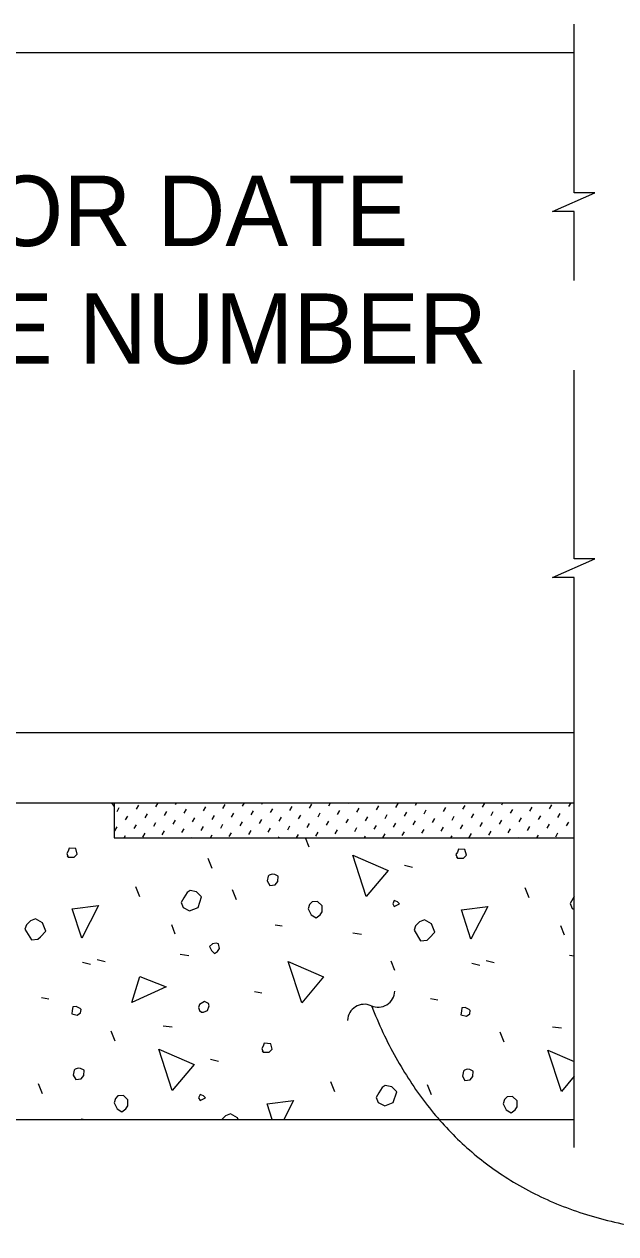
# Model space of a CAD drawing. Extents: x 130583.6 to 130653, y 88618.2 to 88652.9.
# Drawn here: x 130605.355 to 130607.456, y 88633.745 to 88638.043 of the extents above; entities that cross this region are included whole.
import ezdxf

# ---------------------------------------------------------------- set-up
doc = ezdxf.new("R2010")
doc.units = 0
for name, color, linetype in [('Dimension', 7, 'Continuous'), ('Miscellaneous', 7, 'Continuous'), ('TextStructures', 7, 'Continuous'), ('TrafBarrierConc', 7, 'Continuous')]:
    doc.layers.add(name, color=color, linetype=linetype)

msp = doc.modelspace()

# ---------------------------------------------------------------- linework, layer by layer
at = {"layer": 'Dimension'}
for points in [[(130607.3086, 88637.1321), (130607.3086, 88637.3778), (130607.2311, 88637.3778), (130607.3811, 88637.444), (130607.3086, 88637.444), (130607.3086, 88638.0434)], [(130607.3086, 88636.4382), (130607.3086, 88636.8145)], [(130607.3086, 88634.0518), (130607.3086, 88636.0774), (130607.2311, 88636.0774), (130607.3811, 88636.1437), (130607.3086, 88636.1437), (130607.3086, 88636.4382)]]:
    msp.add_lwpolyline(points, dxfattribs=at)
for centre, start, end in [((130606.6114, 88634.61), 245.9128, 357.64), ((130606.5627, 88634.5011), 65.9128, 177.64)]:
    msp.add_arc(centre, 0.0596, start, end, dxfattribs=at)
msp.add_open_spline([(130606.5877, 88634.5559), (130606.9109, 88633.7452), (130607.8406, 88633.7452)], degree=2, dxfattribs=at)
at = {"layer": 'Miscellaneous'}
for p, q in [((130605.8227, 88635.2623), (130605.8308, 88635.2763)), ((130605.8918, 88635.2704), (130605.8955, 88635.2768)), ((130606.1298, 88635.2642), (130606.1371, 88635.2768)), ((130606.199, 88635.2723), (130606.2016, 88635.2768)), ((130606.3679, 88635.258), (130606.376, 88635.272)), ((130606.437, 88635.2661), (130606.4432, 88635.2768)), ((130606.5062, 88635.2742), (130606.5077, 88635.2768)), ((130606.6751, 88635.2598), (130606.6832, 88635.2738)), ((130606.7442, 88635.2679), (130606.7493, 88635.2768)), ((130606.8134, 88635.276), (130606.8138, 88635.2768)), ((130606.9822, 88635.2617), (130606.9903, 88635.2757)), ((130607.0514, 88635.2698), (130607.0554, 88635.2768)), ((130607.2894, 88635.2636), (130607.297, 88635.2768)), ((130605.6843, 88635.2461), (130605.6924, 88635.2601)), ((130605.7149, 88635.2156), (130605.723, 88635.2296)), ((130605.7535, 88635.2542), (130605.7616, 88635.2682)), ((130605.784, 88635.2237), (130605.7921, 88635.2377)), ((130605.8532, 88635.2318), (130605.8613, 88635.2458)), ((130605.9224, 88635.2399), (130605.9305, 88635.2539)), ((130605.9915, 88635.248), (130605.9996, 88635.262)), ((130606.022, 88635.2175), (130606.0302, 88635.2314)), ((130606.0607, 88635.2561), (130606.0688, 88635.2701)), ((130606.0912, 88635.2256), (130606.0993, 88635.2396)), ((130606.1604, 88635.2337), (130606.1685, 88635.2477)), ((130606.2295, 88635.2418), (130606.2376, 88635.2558)), ((130606.2987, 88635.2499), (130606.3068, 88635.2639)), ((130606.3292, 88635.2193), (130606.3373, 88635.2333)), ((130606.3984, 88635.2274), (130606.4065, 88635.2414)), ((130606.4676, 88635.2355), (130606.4757, 88635.2495)), ((130606.5367, 88635.2436), (130606.5448, 88635.2576)), ((130606.6059, 88635.2517), (130606.614, 88635.2657)), ((130606.6364, 88635.2212), (130606.6445, 88635.2352)), ((130606.7056, 88635.2293), (130606.7137, 88635.2433)), ((130606.7748, 88635.2374), (130606.7829, 88635.2514)), ((130606.8439, 88635.2455), (130606.852, 88635.2595)), ((130606.8744, 88635.215), (130606.8825, 88635.229)), ((130606.9131, 88635.2536), (130606.9212, 88635.2676)), ((130606.9436, 88635.2231), (130606.9517, 88635.2371)), ((130607.0128, 88635.2312), (130607.0209, 88635.2452)), ((130607.0819, 88635.2393), (130607.09, 88635.2533)), ((130607.1511, 88635.2474), (130607.1592, 88635.2614)), ((130607.1816, 88635.2169), (130607.1897, 88635.2309)), ((130607.2203, 88635.2555), (130607.2284, 88635.2695)), ((130607.2508, 88635.225), (130607.2589, 88635.239)), ((130605.6762, 88635.1769), (130605.6843, 88635.1909)), ((130605.7454, 88635.185), (130605.7535, 88635.199)), ((130605.8146, 88635.1931), (130605.8227, 88635.2071)), ((130605.8837, 88635.2013), (130605.8918, 88635.2152)), ((130605.9529, 88635.2094), (130605.961, 88635.2233)), ((130605.9834, 88635.1788), (130605.9915, 88635.1928)), ((130606.0526, 88635.1869), (130606.0607, 88635.2009)), ((130606.1217, 88635.195), (130606.1298, 88635.209)), ((130606.1909, 88635.2031), (130606.199, 88635.2171)), ((130606.2214, 88635.1726), (130606.2295, 88635.1866)), ((130606.2601, 88635.2112), (130606.2682, 88635.2252)), ((130606.2906, 88635.1807), (130606.2987, 88635.1947)), ((130606.3598, 88635.1888), (130606.3679, 88635.2028)), ((130606.4289, 88635.1969), (130606.437, 88635.2109)), ((130606.4981, 88635.205), (130606.5062, 88635.219)), ((130606.5286, 88635.1745), (130606.5367, 88635.1885)), ((130606.5673, 88635.2131), (130606.5754, 88635.2271)), ((130606.5978, 88635.1826), (130606.6059, 88635.1966)), ((130606.667, 88635.1907), (130606.6751, 88635.2047)), ((130606.7361, 88635.1988), (130606.7442, 88635.2128)), ((130606.8053, 88635.2069), (130606.8134, 88635.2209)), ((130606.8358, 88635.1764), (130606.8439, 88635.1903)), ((130606.905, 88635.1845), (130606.9131, 88635.1985)), ((130606.9741, 88635.1926), (130606.9822, 88635.2066)), ((130607.0433, 88635.2007), (130607.0514, 88635.2147)), ((130607.1125, 88635.2088), (130607.1206, 88635.2228)), ((130607.143, 88635.1782), (130607.1511, 88635.1922)), ((130607.2122, 88635.1863), (130607.2203, 88635.2003)), ((130607.2813, 88635.1944), (130607.2894, 88635.2084)), ((130605.7099, 88635.1518), (130605.7149, 88635.1604)), ((130605.7759, 88635.1545), (130605.784, 88635.1685)), ((130605.8451, 88635.1626), (130605.8532, 88635.1766)), ((130605.9143, 88635.1707), (130605.9224, 88635.1847)), ((130605.9515, 88635.1518), (130605.9529, 88635.1542)), ((130606.016, 88635.1518), (130606.022, 88635.1623)), ((130606.0831, 88635.1564), (130606.0912, 88635.1704)), ((130606.1523, 88635.1645), (130606.1604, 88635.1785)), ((130606.2576, 88635.1518), (130606.2601, 88635.1561)), ((130606.3221, 88635.1518), (130606.3292, 88635.1642)), ((130606.3666, 88635.1191), (130606.3535, 88635.1518)), ((130606.3903, 88635.1583), (130606.3984, 88635.1723)), ((130606.4595, 88635.1664), (130606.4676, 88635.1804)), ((130606.5637, 88635.1518), (130606.5673, 88635.1579)), ((130606.6283, 88635.152), (130606.6364, 88635.166)), ((130606.6975, 88635.1601), (130606.7056, 88635.1741)), ((130606.7666, 88635.1683), (130606.7748, 88635.1822)), ((130606.8698, 88635.1518), (130606.8744, 88635.1598)), ((130606.9355, 88635.1539), (130606.9436, 88635.1679)), ((130607.0047, 88635.162), (130607.0128, 88635.176)), ((130607.0738, 88635.1701), (130607.0819, 88635.1841)), ((130607.1114, 88635.1518), (130607.1125, 88635.1536)), ((130607.1759, 88635.1518), (130607.1816, 88635.1617)), ((130607.2427, 88635.1558), (130607.2508, 88635.1698)), ((130606.0218, 88635.043), (130606.0077, 88635.0784)), ((130606.706, 88635.0554), (130606.7342, 88635.0483)), ((130605.7655, 88634.9423), (130605.7514, 88634.9776)), ((130607.1479, 88634.9387), (130607.1338, 88634.9741)), ((130606.1085, 88634.9317), (130606.0943, 88634.967)), ((130605.891, 88634.8097), (130605.8786, 88634.8433)), ((130606.2463, 88634.8433), (130606.2711, 88634.8398)), ((130606.5221, 88634.815), (130606.5522, 88634.8097)), ((130607.2734, 88634.8062), (130607.261, 88634.8398)), ((130605.6135, 88634.7195), (130605.6418, 88634.7125)), ((130605.9087, 88634.739), (130605.9388, 88634.7337)), ((130606.6706, 88634.6807), (130606.6582, 88634.7142)), ((130606.9959, 88634.716), (130607.0242, 88634.7089)), ((130607.2911, 88634.7355), (130607.3087, 88634.7324)), ((130605.5622, 88634.7107), (130605.5905, 88634.7036)), ((130606.9446, 88634.7072), (130606.9729, 88634.7001)), ((130605.4155, 88634.5852), (130605.442, 88634.5799)), ((130606.1721, 88634.6064), (130606.1986, 88634.6011)), ((130606.7979, 88634.5817), (130606.8244, 88634.5764)), ((130605.6771, 88634.4296), (130605.663, 88634.465)), ((130605.8486, 88634.4844), (130605.8804, 88634.4809)), ((130607.0595, 88634.4261), (130607.0454, 88634.4615)), ((130607.231, 88634.4809), (130607.2628, 88634.4774)), ((130606.0165, 88634.366), (130606.0448, 88634.3589)), ((130606.4585, 88634.2493), (130606.4443, 88634.2847)), ((130605.419, 88634.2422), (130605.4049, 88634.2776)), ((130606.8014, 88634.2387), (130606.7873, 88634.2741)), ((130605.5569, 88634.1539), (130605.5716, 88634.1518))]:
    msp.add_line(p, q, dxfattribs=at)
for points in [[(130605.6745, 88635.265), (130605.6656, 88635.2768)], [(130605.511, 88635.0837), (130605.5322, 88635.0837), (130605.5428, 88635.0943), (130605.5375, 88635.1138), (130605.5145, 88635.1155), (130605.511, 88635.1049), (130605.5056, 88635.0961), (130605.511, 88635.0837), (130605.5074, 88635.0872)], [(130606.8933, 88635.0802), (130606.9146, 88635.0802), (130606.9252, 88635.0908), (130606.9199, 88635.1102), (130606.8969, 88635.112), (130606.8933, 88635.1014), (130606.888, 88635.0925), (130606.8933, 88635.0802), (130606.8898, 88635.0837)], [(130606.5698, 88634.9441), (130606.5221, 88635.0908), (130606.6476, 88635.036), (130606.5698, 88634.9441)], [(130606.2181, 88634.9989), (130606.2269, 88634.9829), (130606.2463, 88634.9847), (130606.2552, 88634.9971), (130606.2569, 88635.0165), (130606.2446, 88635.0218), (130606.2357, 88635.0236), (130606.2251, 88635.0201), (130606.2216, 88635.0165), (130606.2181, 88634.9989)], [(130605.9193, 88634.9052), (130605.9423, 88634.8928), (130605.9723, 88634.9052), (130605.9847, 88634.9423), (130605.967, 88634.96), (130605.9441, 88634.9653), (130605.9334, 88634.9582), (130605.9211, 88634.9387), (130605.9122, 88634.9228), (130605.9193, 88634.9052)], [(130606.6688, 88634.9087), (130606.6883, 88634.9175), (130606.6812, 88634.9246), (130606.6688, 88634.9299), (130606.6635, 88634.9175), (130606.6688, 88634.9087)], [(130607.3087, 88634.9434), (130607.3035, 88634.9352), (130607.2946, 88634.9193), (130607.3017, 88634.9016)], [(130605.5587, 88634.7956), (130605.5251, 88634.8999), (130605.6188, 88634.9122), (130605.5587, 88634.7956)], [(130606.363, 88634.8999), (130606.3736, 88634.8786), (130606.3913, 88634.868), (130606.4054, 88634.8786), (130606.4125, 88634.8892), (130606.4125, 88634.9105), (130606.3966, 88634.9264), (130606.3772, 88634.9246), (130606.3683, 88634.9158), (130606.363, 88634.8999)], [(130606.9411, 88634.792), (130606.9075, 88634.8963), (130607.0012, 88634.9087), (130606.9411, 88634.792)], [(130607.3017, 88634.9016), (130607.3087, 88634.8979)], [(130605.3572, 88634.8274), (130605.3801, 88634.7903), (130605.4031, 88634.792), (130605.412, 88634.8009), (130605.4314, 88634.8203), (130605.419, 88634.8504), (130605.3943, 88634.8645), (130605.3766, 88634.8574), (130605.3625, 88634.8433), (130605.3572, 88634.8274)], [(130606.7395, 88634.8238), (130606.7625, 88634.7867), (130606.7855, 88634.7885), (130606.7943, 88634.7973), (130606.8138, 88634.8168), (130606.8014, 88634.8468), (130606.7767, 88634.861), (130606.759, 88634.8539), (130606.7449, 88634.8398), (130606.7395, 88634.8238)], [(130606.0201, 88634.7514), (130606.0307, 88634.7408), (130606.0413, 88634.7478), (130606.0484, 88634.7584), (130606.0448, 88634.7761), (130606.036, 88634.7779), (130606.0236, 88634.7761), (130606.013, 88634.7655), (130606.0201, 88634.7514)], [(130606.3405, 88634.566), (130606.2928, 88634.7128), (130606.4183, 88634.658), (130606.3405, 88634.566)], [(130605.7372, 88634.5675), (130605.7655, 88634.6594), (130605.8592, 88634.6223), (130605.7372, 88634.5675)], [(130605.5233, 88634.5269), (130605.5428, 88634.5216), (130605.5551, 88634.5304), (130605.5569, 88634.5428), (130605.5534, 88634.5463), (130605.5392, 88634.5534), (130605.5269, 88634.5516), (130605.5251, 88634.5392), (130605.5233, 88634.5269)], [(130605.9847, 88634.5322), (130605.9918, 88634.5322), (130606.0059, 88634.5392), (130606.0112, 88634.5551), (130606.0095, 88634.564), (130605.9953, 88634.5711), (130605.9776, 88634.5604), (130605.9741, 88634.5498), (130605.9776, 88634.5392), (130605.9847, 88634.5322)], [(130606.9057, 88634.5233), (130606.9252, 88634.518), (130606.9375, 88634.5269), (130606.9393, 88634.5392), (130606.9358, 88634.5428), (130606.9216, 88634.5498), (130606.9093, 88634.5481), (130606.9075, 88634.5357), (130606.9057, 88634.5233)], [(130606.2039, 88634.3907), (130606.2251, 88634.3907), (130606.2357, 88634.4013), (130606.2304, 88634.4208), (130606.2075, 88634.4226), (130606.2039, 88634.412), (130606.1986, 88634.4031), (130606.2039, 88634.3907), (130606.2004, 88634.3943)], [(130605.8804, 88634.2546), (130605.8327, 88634.4013), (130605.9582, 88634.3465), (130605.8804, 88634.2546)], [(130607.2628, 88634.2511), (130607.2151, 88634.3978), (130607.3087, 88634.3569)], [(130605.5286, 88634.3094), (130605.5375, 88634.2935), (130605.5569, 88634.2953), (130605.5658, 88634.3077), (130605.5675, 88634.3271), (130605.5551, 88634.3324), (130605.5463, 88634.3342), (130605.5357, 88634.3306), (130605.5322, 88634.3271), (130605.5286, 88634.3094)], [(130606.911, 88634.3059), (130606.9199, 88634.29), (130606.9393, 88634.2917), (130606.9481, 88634.3041), (130606.9499, 88634.3236), (130606.9375, 88634.3289), (130606.9287, 88634.3306), (130606.9181, 88634.3271), (130606.9146, 88634.3236), (130606.911, 88634.3059)], [(130607.3087, 88634.3053), (130607.2628, 88634.2511)], [(130605.9794, 88634.2193), (130605.9989, 88634.2281), (130605.9918, 88634.2352), (130605.9794, 88634.2405), (130605.9741, 88634.2281), (130605.9794, 88634.2193)], [(130606.6123, 88634.2122), (130606.6353, 88634.1998), (130606.6653, 88634.2122), (130606.6777, 88634.2493), (130606.66, 88634.267), (130606.637, 88634.2723), (130606.6264, 88634.2652), (130606.614, 88634.2458), (130606.6052, 88634.2299), (130606.6123, 88634.2122)], [(130605.6736, 88634.2104), (130605.6842, 88634.1892), (130605.7019, 88634.1786), (130605.716, 88634.1892), (130605.7231, 88634.1998), (130605.7231, 88634.221), (130605.7072, 88634.2369), (130605.6877, 88634.2352), (130605.6789, 88634.2263), (130605.6736, 88634.2104)], [(130606.2358, 88634.1518), (130606.2181, 88634.2069), (130606.3117, 88634.2193), (130606.277, 88634.1518)], [(130607.056, 88634.2069), (130607.0666, 88634.1857), (130607.0843, 88634.1751), (130607.0984, 88634.1857), (130607.1055, 88634.1963), (130607.1055, 88634.2175), (130607.0896, 88634.2334), (130607.0701, 88634.2316), (130607.0613, 88634.2228), (130607.056, 88634.2069)], [(130606.1143, 88634.1518), (130606.112, 88634.1574), (130606.0872, 88634.1715), (130606.0696, 88634.1645), (130606.0569, 88634.1518)]]:
    msp.add_lwpolyline(points, dxfattribs=at)
at = {"layer": 'TrafBarrierConc'}
for p, q in [((130603.6745, 88637.9434), (130607.3086, 88637.9434)), ((130603.6745, 88635.5268), (130607.3086, 88635.5268)), ((130603.6745, 88635.2768), (130607.3086, 88635.2768)), ((130605.6745, 88635.2768), (130605.6745, 88635.1518)), ((130605.6745, 88635.1518), (130607.3087, 88635.1518)), ((130605.2918, 88634.1518), (130607.3086, 88634.1518))]:
    msp.add_line(p, q, dxfattribs=at)

# ---------------------------------------------------------------- texts
at = {"layer": 'TextStructures'}
for s, p in [('NAME OR DATE', (130604.1743, 88637.2551)), ('BRIDGE NUMBER', (130604.1743, 88636.8369))]:
    msp.add_text(s, height=0.250048, dxfattribs=at).set_placement(p)

doc.saveas('drawing.dxf')
